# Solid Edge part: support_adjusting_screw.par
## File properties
Title: Support adjusting screw
Author: Robert a Rhodes jr
Template: Normal.par
Last saved by: Cadcim
Revision: 14
Application: Solid Edge
Material: aluminum
Accuracy: 0.99
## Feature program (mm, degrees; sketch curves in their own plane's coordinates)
sketch for "unnamed Protrusion 1" plane through (0, 0, 0) normal (0, -1, 0) x-axis (1, 0, 0)
  circle centre (0, 0) radius 38.1
extrude "unnamed Protrusion 1" add finite 584.2 along +normal
sketch for "ExtrudedCutout_1" plane through (0, -520.7, 0) normal (0, -1, 0) x-axis (1, 0, 0)
extrude "ExtrudedCutout_1" cut finite 76.2 along +normal  Plane_Distance = 63.5 mm
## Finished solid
Body 1: solid body, 5 faces, 4 edges, 0 vertices.
  Faces by surface: plane 3, cylinder 2
  Edges by curve: circle 4
Bounding box of the edges (mm): 76.200 x 584.200 x 76.200, from (-38.1, -584.2, -38.1) to (38.1, 0, 38.1).
Cylindrical faces by radius (mm): R25.4 x1, R38.1 x1
Planar faces by outward normal: +y 1, -y 2
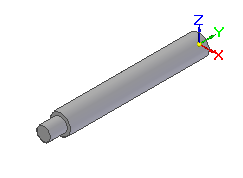
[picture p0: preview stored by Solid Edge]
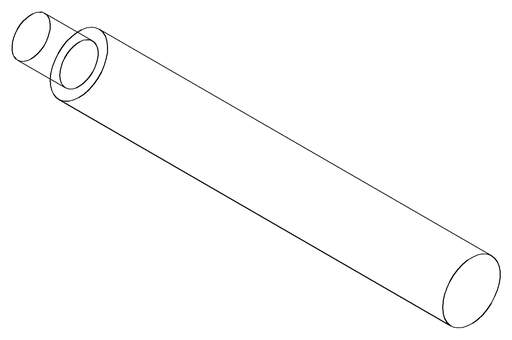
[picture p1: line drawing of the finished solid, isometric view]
